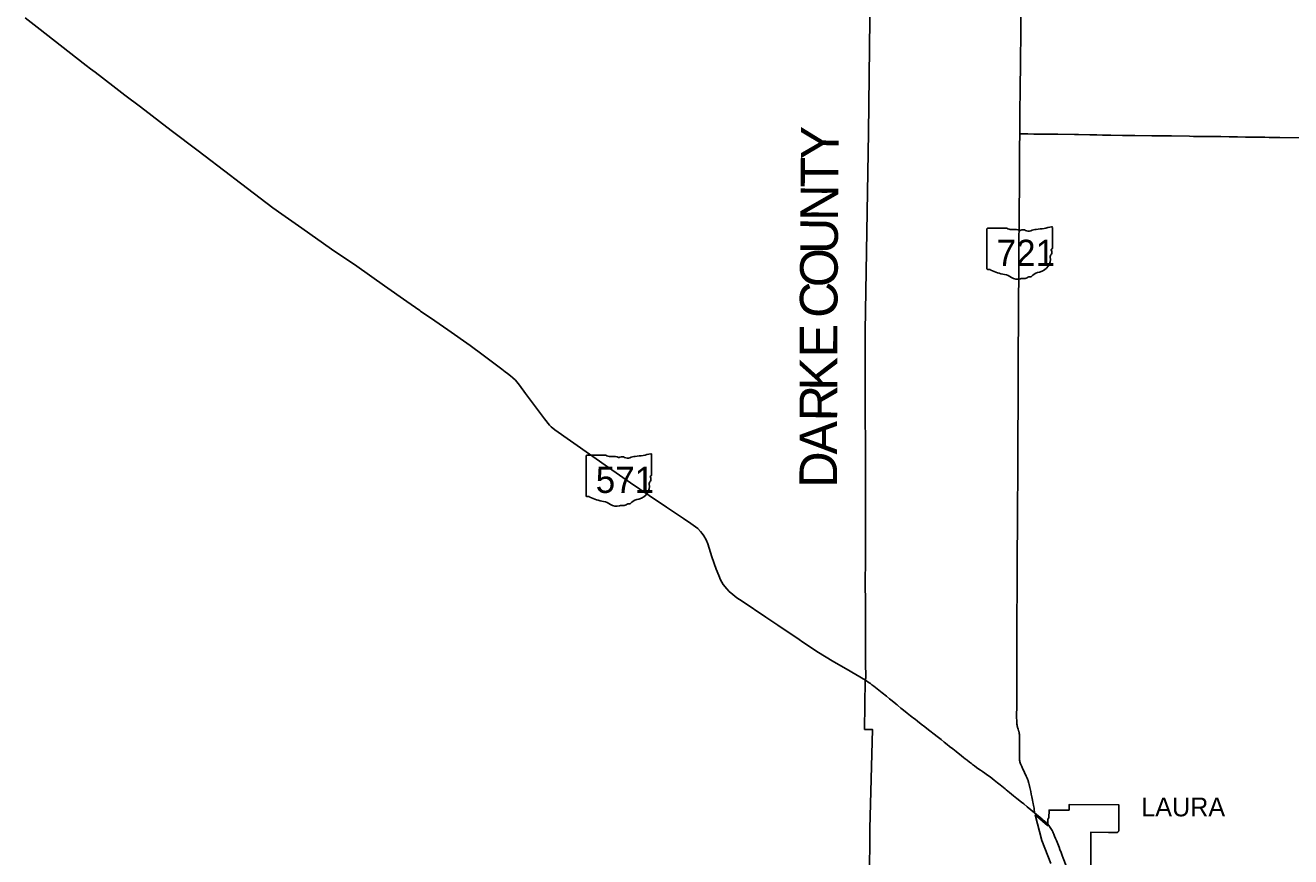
# Model space of a CAD drawing. Extents: x 0 to 34, y 0 to 22.
# Drawn here: x 3.904 to 4.445, y 16.586 to 16.941 of the extents above; entities that cross this region are included whole.
import ezdxf

# ---------------------------------------------------------------- set-up
doc = ezdxf.new("R2010")
doc.units = 0
for name, color, linetype in [('GM_X_Corporation', 7, 'Continuous'), ('GM_X_Corporation_Text', 7, 'Continuous'), ('GM_X_County', 7, 'Continuous'), ('GM_X_County_Text', 7, 'Continuous'), ('GM_X_State_Location', 7, 'Continuous'), ('GM_X_State_Route', 7, 'Continuous'), ('GM_X_State_Shield', 7, 'Continuous')]:
    doc.layers.add(name, color=color, linetype=linetype)

msp = doc.modelspace()

# ---------------------------------------------------------------- linework, layer by layer
at = {"layer": 'GM_X_Corporation'}
msp.add_lwpolyline([(4.3422, 16.58264), (4.33836, 16.59258), (4.33548, 16.60344), (4.34076, 16.59895), (4.34082, 16.5995), (4.34082, 16.60161), (4.34132, 16.60224), (4.3414, 16.60556), (4.34995, 16.60555), (4.34995, 16.6079), (4.37121, 16.60784), (4.37114, 16.59663), (4.3711, 16.59651), (4.37105, 16.59641), (4.37098, 16.59631), (4.3709, 16.59622), (4.37078, 16.59612), (4.3707, 16.59607), (4.3706, 16.59601), (4.37052, 16.59598), (4.3704, 16.59595), (4.37027, 16.59592), (4.37013, 16.5959), (4.37, 16.5959), (4.36686, 16.59593), (4.35925, 16.59606), (4.3592, 16.56821)], dxfattribs=at)
at = {"layer": 'GM_X_County'}
for points in [[(4.26457, 16.5527), (4.26488, 16.59763), (4.26592, 16.64002), (4.26264, 16.64004), (4.26291, 16.66108), (4.26301, 16.66151), (4.26304, 16.66168), (4.26307, 16.6619), (4.26308, 16.66208), (4.26308, 16.6625), (4.26307, 16.66322), (4.26303, 16.66769), (4.26302, 16.66979), (4.26301, 16.67086), (4.26299, 16.67312), (4.26298, 16.67554), (4.26297, 16.67719), (4.26296, 16.67928), (4.26296, 16.6808), (4.26296, 16.68391), (4.26297, 16.68553), (4.26297, 16.68799), (4.26297, 16.6915), (4.26294, 16.69629), (4.26292, 16.70039), (4.26292, 16.70215), (4.26291, 16.70317), (4.26291, 16.70435), (4.2629, 16.70537), (4.26295, 16.70963), (4.26296, 16.7121), (4.26297, 16.71421), (4.26297, 16.7164), (4.26298, 16.7185), (4.26298, 16.72043), (4.263, 16.72341), (4.26301, 16.72412), (4.26302, 16.72578), (4.26291, 16.81041), (4.26421, 16.8951), (4.26523, 16.97998)], [(4.26523, 16.97998), (4.26421, 16.8951), (4.26291, 16.81041), (4.26302, 16.72578), (4.26301, 16.72412), (4.263, 16.72341), (4.26298, 16.72043), (4.26298, 16.7185), (4.26297, 16.7164), (4.26297, 16.71421), (4.26296, 16.7121), (4.26295, 16.70963), (4.2629, 16.70537), (4.26291, 16.70435), (4.26291, 16.70317), (4.26292, 16.70215), (4.26292, 16.70039), (4.26294, 16.69629), (4.26297, 16.6915), (4.26297, 16.68799), (4.26297, 16.68553), (4.26296, 16.68391), (4.26296, 16.6808), (4.26296, 16.67928), (4.26297, 16.67719), (4.26298, 16.67554), (4.26299, 16.67312), (4.26301, 16.67086), (4.26302, 16.66979), (4.26303, 16.66769), (4.26307, 16.66322), (4.26308, 16.6625), (4.26308, 16.66208), (4.26307, 16.6619), (4.26304, 16.66168), (4.26301, 16.66151), (4.26291, 16.66108), (4.26264, 16.64004), (4.26592, 16.64002), (4.26488, 16.59763), (4.26457, 16.5527)]]:
    msp.add_lwpolyline(points, dxfattribs=at)
at = {"layer": 'GM_X_State_Route'}
for points in [[(3.9041, 16.94422), (3.90918, 16.9402)], [(3.90918, 16.9402), (3.93003, 16.92378), (3.93195, 16.92234), (3.9339, 16.92094), (3.94143, 16.91514), (3.94668, 16.91115), (3.95328, 16.90619), (3.96643, 16.89607), (3.97792, 16.88729), (3.99177, 16.87678), (3.99353, 16.87538)], [(4.32907, 16.91427), (4.3291, 16.91723), (4.32915, 16.92134), (4.32918, 16.92387), (4.32918, 16.92519), (4.32918, 16.92835), (4.32925, 16.93099), (4.32928, 16.93262), (4.32929, 16.93468), (4.32932, 16.93657), (4.32933, 16.9381), (4.3294, 16.94501)], [(4.3284, 16.63947), (4.32837, 16.63955), (4.32816, 16.64018), (4.32805, 16.64052), (4.32795, 16.64083), (4.32788, 16.6411), (4.3278, 16.64142), (4.32772, 16.64187), (4.32767, 16.64224), (4.32762, 16.64272), (4.32759, 16.64319), (4.32757, 16.64364), (4.32755, 16.64511), (4.32757, 16.6507), (4.32759, 16.65418), (4.32759, 16.65692), (4.3276, 16.65918), (4.32761, 16.66093), (4.32761, 16.66287), (4.32762, 16.66482), (4.32765, 16.6694), (4.32766, 16.67099), (4.32765, 16.67367), (4.32766, 16.67895), (4.32769, 16.6847), (4.32771, 16.6906), (4.32776, 16.69719), (4.32779, 16.70405), (4.32782, 16.7089), (4.32783, 16.71201), (4.32785, 16.71665), (4.32792, 16.72537), (4.32794, 16.72799), (4.32794, 16.73052), (4.32796, 16.73421), (4.32798, 16.73917), (4.328, 16.74455), (4.32802, 16.74818), (4.32804, 16.75267), (4.32806, 16.75667), (4.32808, 16.76189), (4.32809, 16.76659), (4.32814, 16.77787), (4.32818, 16.78388), (4.32819, 16.78473), (4.32819, 16.78552), (4.32819, 16.78604), (4.3282, 16.78694), (4.32822, 16.79427), (4.32823, 16.79696), (4.32826, 16.80249), (4.32827, 16.80587), (4.3283, 16.80999), (4.3283, 16.81561), (4.32836, 16.82109), (4.32838, 16.82441), (4.32849, 16.83333), (4.32851, 16.84466), (4.32856, 16.85073), (4.32859, 16.85389), (4.32866, 16.86191), (4.32867, 16.86491), (4.32872, 16.86934), (4.32871, 16.87214), (4.32877, 16.88068), (4.3288, 16.88495), (4.32882, 16.8888), (4.32887, 16.89459), (4.32888, 16.89582), (4.32891, 16.89967), (4.32894, 16.90156), (4.32897, 16.90568), (4.32904, 16.91174), (4.32907, 16.91427)], [(4.32887, 16.89459), (4.32946, 16.89458), (4.3302, 16.89458), (4.3324, 16.89455), (4.33495, 16.89452), (4.33816, 16.89447), (4.34106, 16.89444), (4.34301, 16.89441), (4.34512, 16.8944), (4.35224, 16.8943), (4.35393, 16.89426), (4.35883, 16.89418), (4.36178, 16.89412), (4.36426, 16.89411), (4.36785, 16.89404), (4.37275, 16.89395), (4.3756, 16.8939), (4.37808, 16.89388), (4.38535, 16.89381), (4.38968, 16.89375), (4.39307, 16.89371), (4.39374, 16.8937), (4.40138, 16.89358), (4.40307, 16.89354), (4.40866, 16.89347), (4.41151, 16.89345), (4.41483, 16.8934), (4.41831, 16.89333), (4.42189, 16.89329), (4.42537, 16.89322), (4.42864, 16.89317), (4.4336, 16.89313), (4.43537, 16.89309), (4.43597, 16.89307), (4.43776, 16.89309), (4.43992, 16.89306), (4.44873, 16.89292)], [(3.99353, 16.87538), (4.0099, 16.86301), (4.01363, 16.86021), (4.02219, 16.85424), (4.03495, 16.84535), (4.04569, 16.83798), (4.05759, 16.82964), (4.06702, 16.82293), (4.07257, 16.81907), (4.07298, 16.81879)], [(4.07298, 16.81879), (4.0791, 16.81461), (4.0846, 16.81087), (4.09406, 16.80415), (4.09965, 16.80004), (4.10761, 16.79404), (4.10913, 16.79288)], [(4.10913, 16.79288), (4.1101, 16.79215), (4.11139, 16.79113), (4.11242, 16.79027), (4.11343, 16.78932), (4.11521, 16.78718), (4.11783, 16.78364), (4.12591, 16.77273), (4.12801, 16.77004), (4.12869, 16.76942), (4.13026, 16.76814), (4.15328, 16.75199), (4.16256, 16.74539), (4.17062, 16.73995), (4.17794, 16.73499), (4.18519, 16.73022), (4.18833, 16.72807), (4.19131, 16.72588), (4.19252, 16.72467), (4.1932, 16.72376), (4.19395, 16.72275), (4.19487, 16.7211), (4.19559, 16.71941), (4.19741, 16.71386), (4.19922, 16.70846), (4.20029, 16.70575), (4.20105, 16.70393), (4.20217, 16.70197), (4.20371, 16.70014), (4.20479, 16.69898), (4.2063, 16.69768), (4.2081, 16.69633), (4.21025, 16.69487), (4.2204, 16.68807), (4.22551, 16.68462), (4.23465, 16.67846), (4.23628, 16.67731), (4.2399, 16.67487), (4.24224, 16.67333), (4.24954, 16.66892), (4.25474, 16.66586), (4.26293, 16.66104)], [(4.26293, 16.66104), (4.26451, 16.65999), (4.26507, 16.6596), (4.26573, 16.65912), (4.26662, 16.65848), (4.26796, 16.65743), (4.27018, 16.65563), (4.2719, 16.65423), (4.27327, 16.65311), (4.27433, 16.65224), (4.27598, 16.65089), (4.27608, 16.65081), (4.27646, 16.6505), (4.27684, 16.65019), (4.27815, 16.64912), (4.27919, 16.64829), (4.28077, 16.64702), (4.28218, 16.64589), (4.28284, 16.64538), (4.28346, 16.6449), (4.28417, 16.64436), (4.28522, 16.64355), (4.28683, 16.6423), (4.28839, 16.64109), (4.28992, 16.63989)], [(4.28992, 16.63989), (4.29051, 16.63943), (4.29227, 16.63804), (4.29355, 16.63702), (4.29528, 16.63565), (4.29656, 16.63464), (4.29787, 16.6336), (4.29893, 16.63276), (4.30032, 16.63166), (4.30172, 16.63055), (4.30399, 16.62874), (4.30489, 16.62802), (4.30564, 16.62743), (4.30642, 16.62683), (4.30745, 16.62603), (4.30824, 16.62542), (4.30869, 16.62507), (4.30949, 16.62447), (4.31041, 16.62379), (4.31142, 16.62306), (4.31215, 16.62254), (4.31292, 16.62203), (4.31396, 16.62133), (4.31515, 16.6205), (4.31619, 16.61973), (4.31715, 16.61902), (4.31795, 16.61839), (4.31936, 16.61726), (4.32045, 16.61639), (4.32189, 16.61522), (4.32268, 16.61458), (4.32314, 16.61421), (4.32451, 16.61309), (4.32623, 16.6117), (4.32763, 16.61056), (4.32961, 16.60894), (4.33058, 16.60815), (4.33204, 16.60695), (4.33364, 16.60565), (4.33522, 16.60437)], [(4.33522, 16.60437), (4.33517, 16.60489), (4.33509, 16.60555), (4.33498, 16.60632), (4.33475, 16.60746), (4.33458, 16.60834), (4.33448, 16.60891), (4.3343, 16.60979), (4.33417, 16.61046), (4.33402, 16.61124), (4.33379, 16.61238), (4.33357, 16.61351), (4.33345, 16.61406), (4.33321, 16.61516), (4.33293, 16.61644), (4.33277, 16.61705), (4.33268, 16.61738), (4.3326, 16.61768), (4.33253, 16.61791), (4.33244, 16.61821), (4.33235, 16.61847), (4.33226, 16.61873), (4.33212, 16.61912), (4.33184, 16.61979), (4.33169, 16.62011), (4.33096, 16.62158), (4.33061, 16.62229), (4.33021, 16.6231), (4.32971, 16.62411), (4.32946, 16.62468), (4.32931, 16.62507), (4.32921, 16.62535), (4.32911, 16.62568), (4.32898, 16.62613), (4.32891, 16.62647), (4.32885, 16.62693), (4.3288, 16.62739), (4.32877, 16.62771), (4.32874, 16.62844), (4.32877, 16.63244), (4.3288, 16.63393), (4.32881, 16.63458), (4.32882, 16.63598), (4.32882, 16.63648), (4.32881, 16.63695), (4.32876, 16.63755), (4.32873, 16.63786), (4.32869, 16.63822), (4.32866, 16.6384), (4.32862, 16.63861), (4.32858, 16.63879), (4.32854, 16.63897), (4.32849, 16.63916), (4.32846, 16.63928), (4.3284, 16.63947)], [(4.33522, 16.60437), (4.33608, 16.60367), (4.33762, 16.60241), (4.33846, 16.60171), (4.33894, 16.6013), (4.33943, 16.60085), (4.34016, 16.60018), (4.34038, 16.59994), (4.34069, 16.59961), (4.34084, 16.59946)], [(4.34084, 16.59946), (4.34127, 16.59892), (4.34189, 16.59812), (4.34222, 16.59766), (4.34249, 16.59724), (4.34269, 16.59687), (4.34302, 16.59625), (4.34322, 16.59582), (4.34349, 16.59519), (4.3438, 16.59445), (4.3442, 16.59342), (4.34454, 16.59254), (4.34483, 16.59179)], [(4.34483, 16.59179), (4.34537, 16.59041), (4.34566, 16.58965), (4.34605, 16.58864), (4.34653, 16.58736), (4.347, 16.58612), (4.34745, 16.58493), (4.3487, 16.58169), (4.34909, 16.58072), (4.34928, 16.58029), (4.34946, 16.5799), (4.34971, 16.57943)]]:
    msp.add_lwpolyline(points, dxfattribs=at)
at = {"layer": 'GM_X_State_Shield'}
for p, q in [((4.31489, 16.85393), (4.31489, 16.83694)), ((4.32335, 16.85422), (4.31516, 16.85422)), ((4.34286, 16.84575), (4.34286, 16.85464)), ((4.34286, 16.84576), (4.34286, 16.84575)), ((4.14364, 16.7569), (4.14364, 16.73991)), ((4.15211, 16.75719), (4.14392, 16.75719)), ((4.17161, 16.74872), (4.17161, 16.75761)), ((4.17161, 16.74873), (4.17161, 16.74872))]:
    msp.add_line(p, q, dxfattribs=at)
for centre, major_axis, start_param, end_param in [((4.31521, 16.85396), (0.000324, 0), 1.712693, 3.28349), ((4.3253, 16.85619), (0.00314, 0), 4.042523, 4.731795), ((4.32635, 16.84468), (0.01128, 0), 1.404758, 1.657858), ((4.32891, 16.85405), (0.000907, 0), 3.836095, 5.185415), ((4.33024, 16.85209), (0.00189, 0), 0.950623, 2.079405), ((4.33668, 16.84903), (0.00597, 0), 1.699011, 2.107814), ((4.33289, 16.87737), (0.02966, 0), 4.814394, 5.042369), ((4.34255, 16.85468), (0.000311, 0), 6.141152, 7.989035), ((4.33267, 16.85478), (0.00227, 0), 4.081561, 5.145723), ((4.34397, 16.84204), (0.0021, 0), 2.387724, 3.262537), ((4.34279, 16.8451), (0.000482, 0), 1.883978, 3.671073), ((4.33972, 16.84398), (0.00289, 0), 5.934695, 6.695948), ((4.34253, 16.84572), (0.000333, 0), 5.05454, 6.418171), ((4.33456, 16.84091), (0.00742, 0), 5.101752, 6.440018), ((4.31521, 16.8369), (0.000327, 0), 3.00124, 4.508301), ((4.31526, 16.83864), (0.00249, 0), 4.665946, 4.897461), ((4.31577, 16.83596), (0.0009, 0), 0.519207, 1.627899), ((4.32713, 16.85122), (0.02142, 0), 4.195997, 4.488961), ((4.32074, 16.82931), (0.0067, 0), 0.823519, 1.323587), ((4.32799, 16.83588), (0.00425, 0), 4.026481, 4.996735), ((4.33045, 16.83001), (0.00349, 0), 1.495662, 1.94098), ((4.33076, 16.83461), (0.00227, 0), 4.691044, 5.507374), ((4.33281, 16.83296), (0.000638, 0), 1.147584, 2.315152), ((4.33254, 16.8353), (0.0024, 0), 4.937069, 5.64225), ((4.33768, 16.83217), (0.00406, 0), 1.647645, 2.488434), ((4.14396, 16.75693), (0.000324, 0), 1.712693, 3.28349), ((4.15406, 16.75916), (0.00314, 0), 4.042523, 4.731795), ((4.1551, 16.74765), (0.01128, 0), 1.404758, 1.657858), ((4.15766, 16.75702), (0.000907, 0), 3.836095, 5.185415), ((4.15899, 16.75506), (0.00189, 0), 0.950623, 2.079405), ((4.16143, 16.75775), (0.00227, 0), 4.081561, 5.145723), ((4.16543, 16.752), (0.00597, 0), 1.699011, 2.107814), ((4.16165, 16.78034), (0.02966, 0), 4.814394, 5.042369), ((4.1713, 16.75765), (0.000311, 0), 6.141152, 7.989035), ((4.17273, 16.74501), (0.0021, 0), 2.387724, 3.262537), ((4.17154, 16.74807), (0.000482, 0), 1.883978, 3.671073), ((4.16847, 16.74695), (0.00289, 0), 5.934695, 6.695948), ((4.17128, 16.74869), (0.000333, 0), 5.05454, 6.418171), ((4.16331, 16.74388), (0.00742, 0), 5.101752, 6.440018), ((4.14396, 16.73987), (0.000327, 0), 3.00124, 4.508301), ((4.14401, 16.74161), (0.00249, 0), 4.665946, 4.897461), ((4.14452, 16.73893), (0.0009, 0), 0.519207, 1.627899), ((4.15588, 16.75419), (0.02142, 0), 4.195997, 4.488961), ((4.14949, 16.73228), (0.0067, 0), 0.823519, 1.323587), ((4.15674, 16.73885), (0.00425, 0), 4.026481, 4.996735), ((4.1592, 16.73297), (0.00349, 0), 1.495662, 1.94098), ((4.15951, 16.73758), (0.00227, 0), 4.691044, 5.507374), ((4.16156, 16.73593), (0.000638, 0), 1.147584, 2.315152), ((4.16129, 16.73827), (0.0024, 0), 4.937069, 5.64225), ((4.16644, 16.73514), (0.00406, 0), 1.647645, 2.488434)]:
    msp.add_ellipse(centre, major_axis=major_axis, ratio=0.8, start_param=start_param, end_param=end_param, dxfattribs=at)

# ---------------------------------------------------------------- texts
at = {"layer": 'GM_X_Corporation_Text'}
msp.add_text('LAURA', height=0.008037, rotation=0, dxfattribs=at).set_placement((4.38078, 16.60286))
at = {"layer": 'GM_X_County_Text'}
for s, rotation, p in [('Y', 89.6173, (4.25144, 16.88357)), ('T', 89.6173, (4.25136, 16.87157)), ('N', 89.617, (4.25127, 16.85738)), ('U', 89.6176, (4.25117, 16.84319)), ('O', 89.6203, (4.25108, 16.829)), ('C', 89.6732, (4.251, 16.8159)), ('E', 89.801, (4.25094, 16.799)), ('K', 89.8932, (4.25091, 16.78482)), ('R', 89.918, (4.25089, 16.77172)), ('A', 89.9184, (4.25087, 16.75753)), ('D', 89.9183, (4.25085, 16.74334))]:
    msp.add_text(s, height=0.01607, rotation=rotation, dxfattribs=at).set_placement(p)
at = {"layer": 'GM_X_State_Location'}
for s, p in [('721', (4.32288, 16.84314)), ('571', (4.15164, 16.7461))]:
    msp.add_text(s, height=0.0000161, rotation=0, dxfattribs=at).set_placement(p)
for s, p in [('s', (4.32856, 16.8443)), ('r', (4.32856, 16.8443)), ('s', (4.15731, 16.74727)), ('r', (4.15731, 16.74727))]:
    msp.add_text(s, height=0.0000161, dxfattribs=at).set_placement(p)
at = {"layer": 'GM_X_State_Shield'}
for s, p in [('721', (4.31901, 16.83814)), ('571', (4.14776, 16.74111))]:
    msp.add_text(s, height=0.011189, dxfattribs=at).set_placement(p)

doc.saveas('drawing.dxf')
